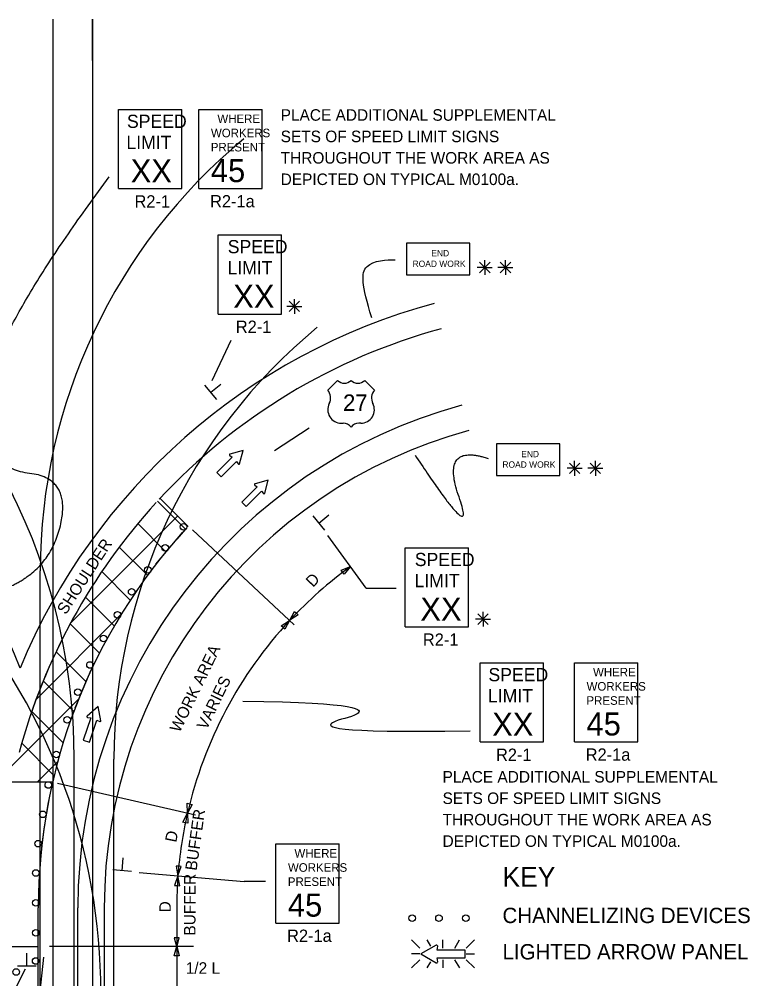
# Model space of a CAD drawing. Extents: x 16728 to 19504, y 5553 to 7079.
# Drawn here: x 16960 to 17404, y 6392 to 6974 of the extents above; entities that cross this region are included whole.
import ezdxf

# ---------------------------------------------------------------- set-up
doc = ezdxf.new("R2010")
doc.units = 0
for name, color, linetype in [('ALI_LEGAL_EX', 7, 'Continuous'), ('MT_SCRATCH_LEVEL_A', 7, 'Continuous'), ('MT_SCRATCH_LEVEL_E', 7, 'Continuous'), ('PAVT_EDGE_EX', 7, 'Continuous'), ('TRAFFIC_SIGNS_PR', 7, 'Continuous'), ('TYPICAL_EX', 7, 'Continuous'), ('TYPICAL_TEXT_DIMEN_EX', 7, 'Continuous'), ('TYPICAL_TEXT_DIMEN_PR', 7, 'Continuous')]:
    doc.layers.add(name, color=color, linetype=linetype)

msp = doc.modelspace()

# ---------------------------------------------------------------- linework, layer by layer
at = {"layer": 'ALI_LEGAL_EX'}
for p, q in [((16980.68, 6974.12), (16980.68, 6155.98)), ((17004.68, 6974.12), (17004.68, 6155.98)), ((16980.68, 6877.04), (16980.68, 6013.12)), ((17004.68, 6877.04), (17004.68, 6013.12)), ((16973.01, 6139.03), (16973.01, 6639.38)), ((16993.65, 6024.8), (16993.65, 6525.15)), ((17017.65, 6024.8), (17017.65, 6525.15)), ((16971.82, 6158.38), (16971.82, 6435.06))]:
    msp.add_line(p, q, dxfattribs=at)
for points in [[(17004.68, 6949.12), (17004.68, 6974.12)], [(17115.18, 6712.56), (17136.15, 6726.16)], [(17043.22, 6643.6), (17059.35, 6662.7)], [(16994.08, 6556.37), (17003.86, 6579.38)], [(16972.46, 6380.33), (16975.08, 6405.19)]]:
    msp.add_lwpolyline(points, dxfattribs=at)
for centre, radius, start, end in [((17313.01, 6639.38), 340, 129.56655, 180), ((16629.65, 6525.15), 364, 0, 57.29578), ((17357.65, 6525.15), 340, 129.56655, 180), ((17311.82, 6435.06), 340, 137.51599, 180), ((16645.75, 6383.76), 364, 0, 40.19088)]:
    msp.add_arc(centre, radius, start, end, dxfattribs=at)
at = {"layer": 'MT_SCRATCH_LEVEL_A'}
for p, q in [((17062.67, 6666.45), (17045.68, 6683.43)), ((17061.07, 6664.68), (17044.08, 6681.66)), ((16991.45, 6607.86), (17056.26, 6672.67)), ((17049.24, 6651.05), (17032.19, 6668.09)), ((17038.09, 6636.74), (17020.94, 6653.89)), ((17027.64, 6621.73), (17010.34, 6639.03)), ((17017.92, 6606), (17000.4, 6623.52)), ((16970.45, 6561.4), (17022.19, 6613.14)), ((17008.93, 6589.53), (16991.15, 6607.31)), ((17000.73, 6572.27), (16982.62, 6590.39)), ((16993.37, 6554.18), (16974.85, 6572.7)), ((16945.7, 6511.2), (16996.34, 6561.84)), ((16986.9, 6535.2), (16967.87, 6554.22)), ((16981.44, 6515.19), (16961.77, 6534.87)), ((16971.15, 6511.2), (16983.54, 6523.59))]:
    msp.add_line(p, q, dxfattribs=at)
for end in [165.00448, 165.00445]:
    msp.add_arc((17311.82, 6435.06), 364, 151.13717, end, dxfattribs=at)
at = {"layer": 'MT_SCRATCH_LEVEL_E'}
for p, q in [((17096.12, 6712.53), (17088.1, 6710.29)), ((17093.96, 6704.47), (17096.12, 6712.53)), ((17089.44, 6708.44), (17080.1, 6699.04)), ((17087.96, 6709.47), (17089.44, 6708.44)), ((17082.75, 6696.4), (17092.1, 6705.8)), ((17092.1, 6705.8), (17093.14, 6704.32)), ((17080.1, 6699.04), (17082.75, 6696.4)), ((17104.67, 6690.48), (17095.33, 6681.08)), ((17103.19, 6691.51), (17104.67, 6690.48)), ((17111.35, 6694.57), (17103.33, 6692.34)), ((17109.19, 6686.52), (17111.35, 6694.57)), ((17097.98, 6678.44), (17107.33, 6687.84)), ((17107.33, 6687.84), (17108.37, 6686.37)), ((17095.33, 6681.08), (17097.98, 6678.44))]:
    msp.add_line(p, q, dxfattribs=at)
for centre, start, end in [((17088.23, 6709.84), 105.58205, 235.12102), ((17093.51, 6704.6), 215.1934, 344.93033), ((17103.46, 6691.89), 105.58205, 235.12102), ((17108.74, 6686.64), 215.1934, 344.93033)]:
    msp.add_arc(centre, 0.463, start, end, dxfattribs=at)
at = {"layer": 'PAVT_EDGE_EX'}
for p, q in [((16980.45, 6511.2), (16939.76, 6511.2)), ((16971.82, 6411.51), (16971.82, 6435.06)), ((16995.69, 6435.06), (16995.69, 6080.11)), ((17011.69, 6435.06), (17011.69, 6080.11)), ((16947.82, 6411.51), (16971.82, 6411.51))]:
    msp.add_line(p, q, dxfattribs=at)
for centre, radius, start, end in [((17311.82, 6435.06), 380, 105.21769, 157.50106), ((16583.82, 6435.06), 404, 21.09612, 61.48623), ((17311.82, 6435.06), 364, 105.21762, 137.08425), ((17311.82, 6435.06), 316, 105.2177, 180), ((17311.82, 6435.06), 300, 105.2177, 180), ((17311.82, 6435.06), 364, 137.51597, 165.0045), ((17311.82, 6435.06), 340, 167.0592, 180)]:
    msp.add_arc(centre, radius, start, end, dxfattribs=at)
at = {"layer": 'TRAFFIC_SIGNS_PR'}
for p, q in [((17020.57, 6919.32), (17058.97, 6919.32)), ((17020.57, 6871.32), (17020.57, 6919.32)), ((17058.97, 6871.32), (17058.97, 6919.32)), ((17069.18, 6919.41), (17107.58, 6919.41)), ((17069.18, 6871.41), (17069.18, 6919.41)), ((17107.58, 6871.41), (17107.58, 6919.41)), ((17020.57, 6871.32), (17058.97, 6871.32)), ((17069.18, 6871.41), (17107.58, 6871.41)), ((17080.99, 6843.27), (17119.39, 6843.27)), ((17080.99, 6795.27), (17080.99, 6843.27)), ((17119.39, 6795.27), (17119.39, 6843.27)), ((17080.99, 6795.27), (17119.39, 6795.27)), ((17194.5, 6653.49), (17232.9, 6653.49)), ((17194.5, 6605.49), (17194.5, 6653.49)), ((17232.9, 6605.49), (17232.9, 6653.49)), ((17194.5, 6605.49), (17232.9, 6605.49)), ((17239.92, 6583.63), (17278.32, 6583.63)), ((17239.92, 6535.63), (17239.92, 6583.63)), ((17278.32, 6535.63), (17278.32, 6583.63)), ((17297.11, 6583.72), (17335.51, 6583.72)), ((17297.11, 6535.72), (17297.11, 6583.72)), ((17335.51, 6535.72), (17335.51, 6583.72)), ((17239.92, 6535.63), (17278.32, 6535.63)), ((17297.11, 6535.72), (17335.51, 6535.72)), ((17115.93, 6473.82), (17154.33, 6473.82)), ((17115.93, 6425.82), (17115.93, 6473.82)), ((17154.33, 6425.82), (17154.33, 6473.82)), ((17115.93, 6425.82), (17154.33, 6425.82)), ((17198.28, 6415.51), (17203.22, 6410.58)), ((17210.05, 6411.69), (17207.84, 6415.52)), ((17217.37, 6410.58), (17217.37, 6415.52)), ((17224.6, 6410.58), (17227.45, 6415.52)), ((17231.52, 6410.58), (17236.45, 6415.52)), ((17203.22, 6407.02), (17198.28, 6407.02)), ((17231.52, 6407.02), (17236.45, 6407.02)), ((17198.28, 6398.54), (17203.22, 6403.47)), ((17207.8, 6398.53), (17209.91, 6402.2)), ((17217.37, 6403.47), (17217.37, 6398.53)), ((17227.5, 6398.53), (17224.65, 6403.47)), ((17231.52, 6403.47), (17236.45, 6398.53))]:
    msp.add_line(p, q, dxfattribs=at)
for points in [[(17195.29, 6819.1), (17233.69, 6819.1), (17233.69, 6838.3), (17195.29, 6838.3)], [(17249.82, 6697.28), (17288.22, 6697.28), (17288.22, 6716.48), (17249.82, 6716.48)]]:
    msp.add_lwpolyline(points, close=True, dxfattribs=at)
for points in [[(17213.29, 6412.3), (17204, 6407.02), (17213.3, 6401.7)], [(17214.17, 6402.33), (17213.77, 6404.6), (17230.78, 6404.6), (17230.78, 6409.4), (17213.77, 6409.4), (17214.17, 6411.68)]]:
    msp.add_lwpolyline(points, dxfattribs=at)
for centre in [(17059.87, 6666.11), (17048.74, 6653.41), (17038.25, 6640.13), (17028.46, 6626.68), (17019.79, 6612.77), (17011.34, 6598.39), (17003.16, 6582.36), (16995.84, 6565.92), (16989.4, 6549.11), (16982.75, 6528), (16977.89, 6509.55), (16974.62, 6491.75), (16971.72, 6473.95), (16970.26, 6456.15), (16970.26, 6437.99), (17198.63, 6428.71), (17214.93, 6428.71), (17231.23, 6428.71), (16970.26, 6419.82), (16970.2, 6402.77), (16958.31, 6396.11)]:
    msp.add_circle(centre, 2, dxfattribs=at)
for centre, radius, start, end in [((17213.58, 6411.78), 0.598, 350.73078, 118.89165), ((17213.58, 6402.23), 0.597, 241.48329, 9.95933)]:
    msp.add_arc(centre, radius, start, end, dxfattribs=at)
at = {"layer": 'TYPICAL_EX'}
for p, q in [((17147.46, 6749.07), (17153.35, 6754.96)), ((17175.76, 6749.07), (17169.86, 6754.96)), ((17155.7, 6729.01), (17156.88, 6729.01)), ((17167.51, 6729.01), (17166.33, 6729.01))]:
    msp.add_line(p, q, dxfattribs=at)
for centre, radius, start, end in [((17157.48, 6759.26), 5.96, 226.14041, 313.85958), ((17165.73, 6759.26), 5.96, 226.14042, 313.85959), ((17141.87, 6744.35), 7.31, 333.09768, 40.19361), ((17181.34, 6744.35), 7.31, 139.80639, 206.90233), ((17155.72, 6737.25), 8.24, 152.6698, 269.90132), ((17167.5, 6737.25), 8.24, 270.09868, 27.3302), ((17156.9, 6723.1), 5.91, 37.1038, 90.13853), ((17166.32, 6723.1), 5.91, 89.86147, 142.8962)]:
    msp.add_arc(centre, radius, start, end, dxfattribs=at)
at = {"layer": 'TYPICAL_TEXT_DIMEN_PR'}
for p, q in [((17242.72, 6823.47), (17238.18, 6823.47)), ((17239.53, 6826.66), (17245.9, 6820.28)), ((17245.9, 6826.66), (17239.53, 6820.28)), ((17242.72, 6823.47), (17242.72, 6827.93)), ((17242.72, 6823.47), (17245.9, 6823.47)), ((17242.72, 6823.47), (17247.19, 6823.47)), ((17242.72, 6823.47), (17242.72, 6818.97)), ((17255.27, 6823.47), (17250.74, 6823.47)), ((17258.46, 6826.66), (17252.08, 6820.28)), ((17252.09, 6826.66), (17258.46, 6820.28)), ((17255.27, 6823.47), (17255.27, 6827.93)), ((17255.27, 6823.47), (17258.46, 6823.47)), ((17255.27, 6823.47), (17259.75, 6823.47)), ((17255.27, 6823.47), (17255.27, 6818.97)), ((17127.19, 6799.89), (17122.66, 6799.89)), ((17124.01, 6803.08), (17130.38, 6796.7)), ((17130.38, 6803.08), (17124.01, 6796.7)), ((17127.19, 6799.89), (17127.19, 6804.34)), ((17127.19, 6799.89), (17130.38, 6799.89)), ((17127.19, 6799.89), (17131.67, 6799.89)), ((17127.19, 6799.89), (17127.19, 6795.39)), ((17077.28, 6754.99), (17088.83, 6779.46)), ((17080.08, 6743.43), (17072.89, 6752.08)), ((17076.48, 6747.76), (17082.47, 6752.73)), ((17297.25, 6701.65), (17292.71, 6701.65)), ((17294.06, 6704.84), (17300.44, 6698.46)), ((17300.44, 6704.84), (17294.06, 6698.46)), ((17297.25, 6701.65), (17297.25, 6706.11)), ((17297.25, 6701.65), (17300.44, 6701.65)), ((17297.25, 6701.65), (17301.72, 6701.65)), ((17297.25, 6701.65), (17297.25, 6697.15)), ((17309.81, 6701.65), (17305.27, 6701.65)), ((17306.62, 6704.84), (17312.99, 6698.46)), ((17312.99, 6704.84), (17306.62, 6698.46)), ((17309.81, 6701.65), (17309.81, 6706.11)), ((17309.81, 6701.65), (17312.99, 6701.65)), ((17309.81, 6701.65), (17314.28, 6701.65)), ((17309.81, 6701.65), (17309.81, 6697.15)), ((17145.69, 6664.12), (17138.51, 6672.77)), ((17142.1, 6668.44), (17148.09, 6673.42)), ((17127.11, 6606.79), (17065.3, 6664.26)), ((17170.75, 6628.99), (17147.51, 6660.94)), ((17155.56, 6639.9), (17161.22, 6642.08)), ((17156.48, 6638.63), (17155.56, 6639.9)), ((17157.41, 6637.36), (17156.48, 6638.63)), ((17161.22, 6642.08), (17157.41, 6637.36)), ((17170.75, 6628.99), (17189.02, 6628.99)), ((17124.44, 6609.48), (17127.28, 6614.84)), ((17127.28, 6614.84), (17128.43, 6613.77)), ((17128.43, 6613.77), (17129.58, 6612.7)), ((17244.87, 6613.29), (17238.49, 6606.91)), ((17238.5, 6613.29), (17244.87, 6606.91)), ((17241.68, 6610.1), (17241.68, 6614.56)), ((17119.19, 6606.15), (17124.33, 6609.37)), ((17124.33, 6609.37), (17121.49, 6604.01)), ((17129.58, 6612.7), (17124.44, 6609.48)), ((17241.68, 6610.1), (17237.15, 6610.1)), ((17241.68, 6610.1), (17244.87, 6610.1)), ((17241.68, 6610.1), (17246.16, 6610.1)), ((17241.68, 6610.1), (17241.68, 6605.6)), ((17120.34, 6605.08), (17119.19, 6606.15)), ((17121.49, 6604.01), (17120.34, 6605.08)), ((17008.1, 6557.26), (17001.45, 6551.37)), ((17009.79, 6548.52), (17008.1, 6557.26)), ((17003.61, 6550.22), (16999.03, 6536.84)), ((17001.7, 6550.52), (17003.61, 6550.22)), ((17002.81, 6535.55), (17007.38, 6548.93)), ((17007.38, 6548.93), (17009.07, 6548)), ((16999.03, 6536.84), (17002.81, 6535.55)), ((17067.19, 6491.27), (16983.42, 6510.52)), ((17062.32, 6492.39), (17062.1, 6498.45)), ((17062.1, 6498.45), (17063.63, 6498.1)), ((17065.16, 6497.75), (17062.32, 6492.39)), ((17063.63, 6498.1), (17065.16, 6497.75)), ((17059.47, 6487.03), (17062.32, 6492.39)), ((17062.32, 6492.39), (17062.54, 6486.32)), ((17061.01, 6486.67), (17059.47, 6487.03)), ((17062.54, 6486.32), (17061.01, 6486.67)), ((17022.72, 6457.54), (17023.37, 6465.3)), ((17028.32, 6457.07), (17017.11, 6458.02)), ((17032.95, 6456.43), (17096.65, 6450.91)), ((17056.99, 6460.23), (17055.42, 6460.36)), ((17055.42, 6460.36), (17056.52, 6454.39)), ((17056.52, 6454.39), (17058.55, 6460.11)), ((17058.55, 6460.11), (17056.99, 6460.23)), ((17056.52, 6454.39), (17054.52, 6448.66)), ((17057.65, 6448.43), (17056.52, 6454.39)), ((17109.71, 6450.91), (17096.65, 6450.91)), ((17054.52, 6448.66), (17056.09, 6448.54)), ((17056.09, 6448.54), (17057.65, 6448.43)), ((17055.79, 6435.06), (17055.79, 6411.86)), ((17055.75, 6416.8), (17054.18, 6416.79)), ((17054.18, 6416.79), (17055.79, 6410.94)), ((17057.32, 6416.81), (17055.75, 6416.8)), ((17055.79, 6410.94), (17057.32, 6416.81)), ((16978.64, 6411.86), (17065.97, 6411.86)), ((17054.22, 6405.99), (17055.79, 6411.86)), ((17055.79, 6411.86), (17055.79, 6381.25)), ((17055.79, 6411.86), (17057.36, 6405.99)), ((16964.8, 6399.68), (16964.8, 6407.47)), ((17055.79, 6405.99), (17054.22, 6405.99)), ((17057.36, 6405.99), (17055.79, 6405.99)), ((16963.92, 6397.9), (16956.54, 6383.4)), ((16970.43, 6399.68), (16959.18, 6399.68))]:
    msp.add_line(p, q, dxfattribs=at)
for centre, radius, start, end in [((17311.82, 6435.06), 256, 126.0328, 137.05056), ((17311.82, 6435.06), 256, 137.08425, 167.0592), ((17001.79, 6551), 0.494, 131.56418, 261.10315), ((17009.3, 6548.44), 0.494, 241.17554, 10.91246), ((17311.82, 6435.06), 256.02, 167.05922, 175.66953), ((17311.82, 6435.06), 256.02, 175.66953, 180)]:
    msp.add_arc(centre, radius, start, end, dxfattribs=at)
for points, degree in [([(16946.2, 6626.92), (16977.56, 6636.36), (16992.5, 6695.83), (16939.3, 6701.55), (16939.4, 6777.31), (17014.81, 6878.41)], 2), ([(17174.09, 6792.93), (17168.08, 6812.93), (17166.72, 6827.64), (17183.51, 6828.25), (17188.39, 6828.04)], 3), ([(17200.44, 6709.72), (17238.68, 6651.54), (17215.46, 6717.25), (17244.82, 6707.66)], 2), ([(17095.89, 6560.43), (17168.69, 6559.53), (17169.01, 6550.86), (17146.7, 6549.04), (17146.46, 6540.95), (17233.91, 6542.48)], 3)]:
    msp.add_open_spline(points, degree=degree, dxfattribs=at)

# ---------------------------------------------------------------- texts
at = {"layer": 'TRAFFIC_SIGNS_PR'}
for s, height, p in [('SPEED', 8, (17025.6, 6908.18)), ('WHERE', 5.2, (17080.49, 6911.09)), ('PLACE ADDITIONAL SUPPLEMENTAL', 7, (17118.88, 6912.51)), ('WORKERS', 5.2, (17076.57, 6902.49)), ('SETS OF SPEED LIMIT SIGNS', 7, (17118.88, 6899.51)), ('LIMIT', 8, (17025.27, 6895.38)), ('PRESENT', 5.2, (17076.5, 6893.89)), ('THROUGHOUT THE WORK AREA AS', 7, (17118.88, 6886.51)), ('XX', 14.031, (17027.88, 6875.08)), ('45', 14.031, (17076.49, 6875.26)), ('DEPICTED ON TYPICAL M0100a.', 7, (17118.88, 6873.51)), ('R2-1', 7.44, (17030.18, 6859.88)), ('R2-1a', 7.44, (17076.04, 6859.97)), ('SPEED', 8, (17086.75, 6832.14)), ('END', 3.831, (17210.29, 6830.22)), ('LIMIT', 8, (17086.59, 6819.34)), ('ROAD WORK', 3.831, (17198.9, 6823.84)), ('XX', 14.031, (17090.1, 6799.03)), ('R2-1', 7.44, (17091.66, 6783.83)), ('END', 3.831, (17264.82, 6708.41)), ('ROAD WORK', 3.831, (17253.43, 6702.02)), ('SPEED', 8, (17200.26, 6642.35)), ('LIMIT', 8, (17200.1, 6629.55)), ('XX', 14.031, (17203.61, 6609.25)), ('R2-1', 7.44, (17205.17, 6594.05)), ('SPEED', 8, (17244.95, 6572.49)), ('WHERE', 5.2, (17308.42, 6575.4)), ('LIMIT', 8, (17244.62, 6559.69)), ('WORKERS', 5.2, (17304.5, 6566.8)), ('PRESENT', 5.2, (17304.43, 6558.2)), ('XX', 14.031, (17247.22, 6539.39)), ('45', 14.031, (17304.42, 6539.57)), ('R2-1a', 7.44, (17303.97, 6524.28)), ('R2-1', 7.44, (17249.53, 6524.19)), ('PLACE ADDITIONAL SUPPLEMENTAL', 7, (17217.11, 6511.02)), ('SETS OF SPEED LIMIT SIGNS', 7, (17217.11, 6498.02)), ('THROUGHOUT THE WORK AREA AS', 7, (17217.11, 6485.02)), ('DEPICTED ON TYPICAL M0100a.', 7, (17217.11, 6472.02)), ('WHERE', 5.2, (17127.24, 6465.5)), ('WORKERS', 5.2, (17123.31, 6456.9)), ('PRESENT', 5.2, (17123.24, 6448.3)), ('45', 14.031, (17123.23, 6429.67)), ('R2-1a', 7.44, (17122.78, 6414.38))]:
    msp.add_text(s, height=height, dxfattribs=at).set_placement(p)
at = {"layer": 'TYPICAL_EX'}
msp.add_text('27', height=10, dxfattribs=at).set_placement((17156.72, 6736.49))
at = {"layer": 'TYPICAL_TEXT_DIMEN_EX'}
for s, height, p in [('KEY', 12, (17253.47, 6447.82)), ('CHANNELIZING DEVICES', 9.3, (17253.47, 6425.77)), ('LIGHTED ARROW PANEL', 9.3, (17253.47, 6403.72))]:
    msp.add_text(s, height=height, dxfattribs=at).set_placement(p)
at = {"layer": 'TYPICAL_TEXT_DIMEN_PR'}
for s, rotation, p in [('SHOULDER', 56.85975, (16988.5, 6612.45)), ('D', 46.92453, (17138.51, 6629.09)), ('WORK AREA', 64.08779, (17057.53, 6540.87)), ('VARIES', 64.08779, (17073.9, 6542.53)), ('BUFFER', 81.87943, (17067.81, 6457.3)), ('D', 78.92264, (17055.49, 6474.4)), ('BUFFER', 89.97949, (17067.19, 6418.19)), ('D', 89.88679, (17052.22, 6432.25))]:
    msp.add_text(s, height=7, rotation=rotation, dxfattribs=at).set_placement(p)
msp.add_text('1/2 L', height=7, dxfattribs=at).set_placement((17061.28, 6395.01))

doc.saveas('drawing.dxf')
